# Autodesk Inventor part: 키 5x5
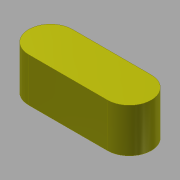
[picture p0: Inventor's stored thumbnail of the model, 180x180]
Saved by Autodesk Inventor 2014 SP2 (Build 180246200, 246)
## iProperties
Created: 2014-10
Part Number: 키 5x5
Document SubType Name: Modeling
Designer: KYOUNG IL JANG
Density: 7.86 g/cm^3
Mass: 2.54015 g
Surface Area: 2.9781 cm^2
Volume: 0.323175 cm^3
Material: 강철, 연강
Appearance: 노란색
Author: SeoGD™ [www.esajin.kr]
Revision Number: 1
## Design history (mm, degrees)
sketch "스케치1"
  geometry: L1 (-4.5, -2.5)-(4.5, -2.5); L2 (4.5, 2.5)-(-4.5, 2.5); A1 r 2.5 centre (4.5, 0) between (4.5, -2.5) and (4.5, 2.5); A2 r 2.5 centre (-4.5, 0) between (-4.5, 2.5) and (-4.5, -2.5); 2 further points
  constraints: 4 end point, 4 point on circle, 4 tangent, 2 centre point, 1 horizontal, 1 horizontal alignment, 1 midpoint, 1 parallel, 1 vertical alignment
  dimensions: "d0" = 5 distance between parallel lines of L1 L2; "d1" = 14 dimension on A1 A2
extrude "돌출1" new body sketch "스케치1" stored distance "d2" = 5; taper "d3" = 0 deg
node "솔리드1"
